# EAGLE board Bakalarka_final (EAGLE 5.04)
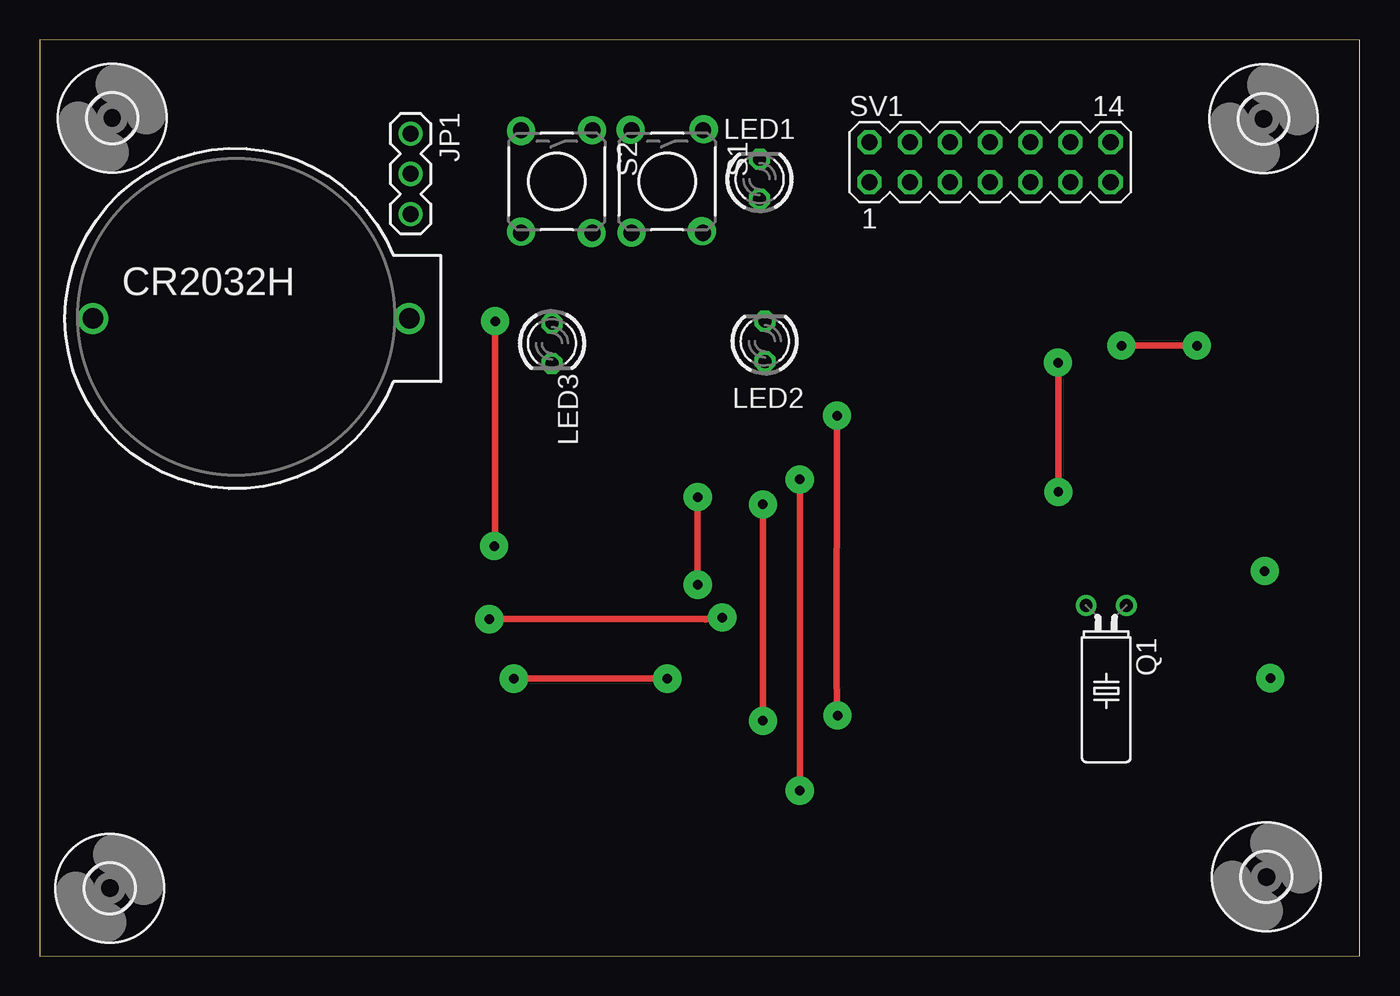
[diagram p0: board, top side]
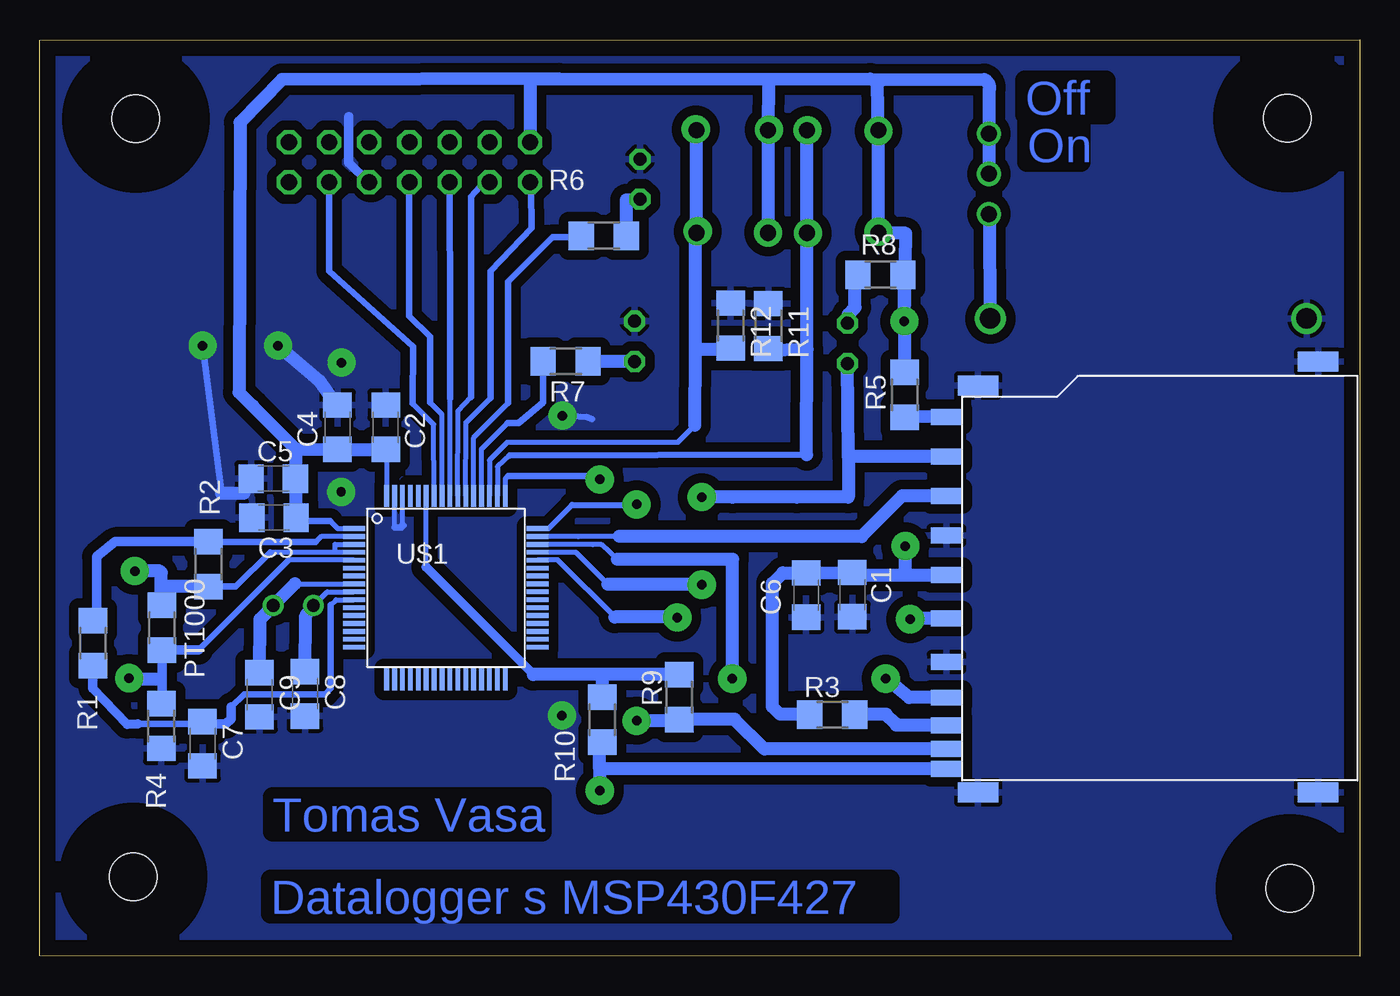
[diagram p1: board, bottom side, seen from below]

Size 83.52 x 57.98 mm. Coordinates in mm from the lower left corner, seen from the top.
Outline: 0,0 83.52,0.03 83.52,57.93 0,57.98 0,0
Copper layers (1*16): Top 0.035mm / dielectric 1.5mm / Bottom 0.035mm
Design rules "default": minimum track width 10mil, minimum drill 24mil, track to track 8mil, track to pad 8mil, pad to pad 8mil, via to via 8mil, smd to smd 8mil, copper to edge 40mil, drill to drill 8mil, minimum pad ring 10mil, minimum via ring 8mil, stop-mask expansion 4mil, vias tented up to drill 0mil, thermal gap 10mil

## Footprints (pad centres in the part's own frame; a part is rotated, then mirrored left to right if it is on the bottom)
C1206 = smd 1.6 x 1.8: 1 -1.4,0; 2 1.4,0
BATTCOM_20MM_PTH = drill 1.3 round: 1 20,0; 2 0,0
1X03 = drill 1.016 round: 1 0,0; 2 2.54,0; 3 5.08,0
LED3MM = drill 0.813 octagon: A -1.27,0; K 1.27,0
R1206 = smd 1.6 x 1.803: 1 -1.422,0; 2 1.422,0
TC38H = drill 0.813 round: 1 -1.27,0; 2 1.27,0
TACTILE-PTH = drill 1.016 round: 1 -3.251,2.261; 2 3.251,2.261; 3 -3.251,-2.261; 4 3.251,-2.261
MA07-2 = drill 1.016 octagon: 1 -7.62,-1.27; 2 -7.62,1.27; 3 -5.08,-1.27; 4 -5.08,1.27; 5 -2.54,-1.27; 6 -2.54,1.27; 7 0,-1.27; 8 0,1.27; 9 2.54,-1.27; 10 2.54,1.27; 11 5.08,-1.27; 12 5.08,1.27; 13 7.62,-1.27; 14 7.62,1.27
PM/PAG64 = smd 1.4 x 0.3: 1 -5.8,3.75; 2 -5.8,3.25; 3 -5.8,2.75; 4 -5.8,2.25; 5 -5.8,1.75; 6 -5.8,1.25; 7 -5.8,0.75; 8 -5.8,0.25; 9 -5.8,-0.25; 10 -5.8,-0.75; 11 -5.8,-1.25; 12 -5.8,-1.75; 13 -5.8,-2.25; 14 -5.8,-2.75; 15 -5.8,-3.25; 16 -5.8,-3.75; 33 5.8,-3.75; 34 5.8,-3.25; 35 5.8,-2.75; 36 5.8,-2.25; 37 5.8,-1.75; 38 5.8,-1.25; 39 5.8,-0.75; 40 5.8,-0.25; 41 5.8,0.25; 42 5.8,0.75; 43 5.8,1.25; 44 5.8,1.75; 45 5.8,2.25; 46 5.8,2.75; 47 5.8,3.25; 48 5.8,3.75 | smd 0.3 x 1.4: 17 -3.75,-5.8; 18 -3.25,-5.8; 19 -2.75,-5.8; 20 -2.25,-5.8; 21 -1.75,-5.8; 22 -1.25,-5.8; 23 -0.75,-5.8; 24 -0.25,-5.8; 25 0.25,-5.8; 26 0.75,-5.8; 27 1.25,-5.8; 28 1.75,-5.8; 29 2.25,-5.8; 30 2.75,-5.8; 31 3.25,-5.8; 32 3.75,-5.8; 49 3.75,5.8; 50 3.25,5.8; 51 2.75,5.8; 52 2.25,5.8; 53 1.75,5.8; 54 1.25,5.8; 55 0.75,5.8; 56 0.25,5.8; 57 -0.25,5.8; 58 -0.75,5.8; 59 -1.25,5.8; 60 -1.75,5.8; 61 -2.25,5.8; 62 -2.75,5.8; 63 -3.25,5.8; 64 -3.75,5.8
3,0 = hole 3: 0,0
SDSOCKET1 = smd 1 x 2: CLK -2.45,17.11; CS 7.8,17.11; DAT1 -9.2,17.11; DAT2 10.3,17.11; DI 5.3,17.11; DO -7.45,17.11; INS -10.7,17.11; VCC 0.3,17.11; VSS 2.8,17.11; VSS1 -5.2,17.11; WP -11.95,17.11 | smd 1.27 x 2.54: PAT1 -13.45,15.11; PAT2 -13.45,-6.39; PAT3 13.8,-6.39; PAT4 12.3,15.11

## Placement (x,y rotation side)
C1  1u  [C1206]  32.11,22.86 270 bottom
C2  1u  [C1206]  61.62,33.45 90 bottom
C3  1u  [C1206]  68.68,27.74 180 bottom
C4  0.01u  [C1206]  64.67,33.45 90 bottom
C5  0.01u  [C1206]  68.73,30.2 180 bottom
C6  0.01u  [C1206]  35.03,22.83 270 bottom
C7  100n  [C1206]  73.2,13.44 270 bottom
C8  5p  [C1206]  66.73,16.59 270 bottom
C9  5p  [C1206]  69.6,16.54 270 bottom
CR2032H  [BATTCOM_20MM_PTH]  3.38,40.34 0 top
JP1  [1X03]  23.47,52.02 270 top
LED1  [LED3MM]  45.54,49.15 90 top
LED2  [LED3MM]  45.87,38.89 90 top
LED3  [LED3MM]  32.41,38.76 270 top
PT1000  1k  [R1206]  75.77,20.78 90 bottom
Q1  32.768kHz  [TC38H]  67.46,22.17 180 top
R1  5k  [R1206]  80.14,19.79 270 bottom
R2  1k  [R1206]  72.82,24.79 90 bottom
R3  50k  [R1206]  33.38,15.27 180 bottom
R4  5k  [R1206]  75.82,14.55 90 bottom
R5  50k  [R1206]  28.8,35.51 90 bottom
R6  330  [R1206]  47.83,45.57 180 bottom
R7  330  [R1206]  50.24,37.62 180 bottom
R8  330  [R1206]  30.33,43.1 0 bottom
R9  100k  [R1206]  43.05,16.38 90 bottom
R10  100k  [R1206]  47.93,14.96 90 bottom
R11  100k  [R1206]  37.41,39.85 270 bottom
R12  100k  [R1206]  39.8,39.88 270 bottom
S1  [TACTILE-PTH]  39.7,49 270 top
S2  [TACTILE-PTH]  32.72,49 270 top
SV1  [MA07-2]  60.12,50.22 0 top
U$1  F42X---PM64  [PM/PAG64]  57.81,23.29 0 bottom
U$2  [3,0]  4.6,53.01 0 top
U$3  SDSOCKET1  [SDSOCKET1]  9.04,23.8 90 bottom
U$4  [3,0]  77.42,52.96 0 top
U$5  [3,0]  77.6,5 0 top
U$6  [3,0]  4.45,4.29 0 top

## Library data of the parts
C1-C9 PT1000 R1-R12 = rcl
CR2032H JP1 S1 S2 = SparkFun
LED1-LED3 = led
Q1 = crystal
SV1 = con-lstb
U$1 = TI_MSP430_v13
U$2 U$4-U$6 = holes
U$3 = SDSOCKET

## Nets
A0+: R1.1 R2.2 U$1.2
A0-/A1+: PT1000.2 R2.1 U$1.3 U$1.4
A1-: PT1000.1 R4.2 U$1.5
BUT1: R12.2 S1.1 S1.2 U$1.51
BUT2: R11.2 S2.1 S2.2 U$1.50
CD: R9.1 U$1.48 U$3.INS
CON: R9.2 R10.2 U$1.59
GND: C1.2 C2.2 C3.2 C4.2 C5.2 C6.2 C7.2 C8.2 C9.2 CR2032H.2 LED1.K LED2.K R4.1 R11.1 R12.1 SV1.9 U$1.62 U$1.63 U$3.PAT1 U$3.PAT2 U$3.PAT3 U$3.PAT4 U$3.VSS U$3.VSS1
LED1: R6.2 U$1.53
LED2: R7.2 U$1.52
N$1: C9.1 Q1.1 U$1.8
N$2: C8.1 Q1.2 U$1.9
N$3: CR2032H.1 JP1.3
N$4: R3.1 U$3.DAT1
N$5: R5.1 U$3.DAT2
N$6: LED1.A R6.1
N$7: LED2.A R7.1
N$8: LED3.A R8.1
RST: SV1.11 U$1.58
SDCS: LED3.K U$1.45 U$3.CS
SIMO: U$1.47 U$3.DI
SOMI: U$1.46 U$3.DO
TCK: SV1.7 U$1.57
TDI: SV1.3 U$1.55
TDO: SV1.1 U$1.54
TMS: SV1.5 U$1.56
UCLK: U$1.44 U$3.CLK
V+: C1.1 C2.1 C3.1 C4.1 C5.1 C6.1 JP1.1 JP1.2 R3.2 R5.2 R8.2 S1.3 S1.4 S2.3 S2.4 SV1.2 U$1.1 U$1.64 U$3.VCC
VREF: C7.1 R1.2 U$1.10
WP: R10.1 U$1.49 U$3.WP

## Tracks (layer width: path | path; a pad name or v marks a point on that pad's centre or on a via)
A0+
  Bottom 0.305: U$1.2 65.71,26.54 66.06,26.19 | 72.8,26.19 R2.2 | 79.91,21.34 R1.1
  Bottom 0.406: 66.06,26.19 72.8,26.19
  Bottom 0.61: R2.2 78.72,26.21 79.91,25.27 79.91,21.34
A0-/A1+
  Bottom 0.305: U$1.3 64.82,26.04 64.82,25.54 | 64.82,25.54 U$1.4 | 64.82,25.54 68.92,25.54 | R2.1
  Bottom 0.406: 68.92,25.54 71.09,23.37 R2.1
  Bottom 0.61: 75.77,23.37 PT1000.2
  Bottom 0.813: R2.1 75.77,23.37
A1-
  Bottom 0.305: 75.77,16.33 R4.2 | U$1.5 67.77,25.04 | PT1000.1
  Bottom 0.406: 67.77,25.04 73.46,19.35
  Bottom 0.61: PT1000.1 75.77,16.33 | 73.46,19.35 PT1000.1
BUT1
  Bottom 0.305: U$1.51 55.06,31.38 53.95,32.49 43.16,32.49 42.06,33.58
  Bottom 0.813: 42.06,33.58 42.04,38.4 | 42.04,38.4 42.01,45.69 S1.2 S1.1 | R12.2 40.03,38.4 42.04,38.4
BUT2
  Bottom 0.305: 53.77,31.67 54.56,30.96 54.56,29.17 U$1.50
  Bottom 0.406: 35,31.72 53.77,31.67
  Bottom 0.813: S2.1 S2.2 34.98,38.38 | 35,31.72 34.98,38.38 | R11.2 37.64,38.3 34.98,38.38
CD  (via drill 0.6 pad 1.78)
  Top 0.406: v45.74,14.88 45.75,18.92 v45.74,28.57
  Bottom 0.305: U$1.48 51.32,27.04 49.84,28.52
  Bottom 0.406: 49.84,28.52 46.1,28.5 v45.74,28.57
  Bottom 0.813: U$3.INS 37.66,13.1 39.55,14.99 39.55,14.96 R9.1 43.05,14.88 v45.74,14.88
CON
  Bottom 0.305: 59.08,24.61 59.08,29.07 U$1.59
  Bottom 0.61: 52.27,17.81 59.08,24.61
  Bottom 0.813: R9.2 47.93,17.8 47.93,17.81 | 47.93,17.81 R10.2 | 47.93,17.81 52.27,17.81
GND  (via drill 0.6 pad 1.78)
  Top 0.406: v73.2,38.61 v68.43,38.61 | v50.44,34.19 50.42,17.48 v50.47,15.21
  Bottom 0.305: 61.06,27.1 U$1.63 | 60.56,27.29 U$1.62
  Bottom 0.406: 72.01,29.26 v73.2,38.61 | 70.59,29.26 arc-45 70.41,29.34 C5.2 | 61.06,27.1 60.63,27.1 60.5,27.23 60.56,27.29 | 48.56,33.96 48.92,34.09 v50.44,34.19 | 64.87,35.05 C4.2 | SV1.9 62.71,48.95 | 63.96,53.09 63.88,53.16
  Bottom 0.61: 62.71,48.95 63.96,50.19 63.96,53.09
  Bottom 0.813: v68.43,38.61 65.86,36.43 64.87,35.05 | 70.59,29.26 72.01,29.26
  other vias: 64.41,37.54 64.44,29.36
  pour Bottom (isolate 0.61): 0.13,0.18 80.14,0.36 83.16,0.36 83.16,0.66 83.19,4.45 83.19,57.56 0.25,57.66 arc90 0,57.4
LED1
  Bottom 0.305: U$1.53 56.06,32.79 53.87,34.98
  Bottom 0.406: R6.2 49.33,45.49 51.05,45.49 53.87,42.67 53.87,34.98
LED2
  Bottom 0.305: U$1.52 55.56,32.07 53.92,33.71
  Bottom 0.406: 53.92,33.71 53.21,33.73 51.66,35 R7.2
N$1
  Bottom 0.305: 67.36,23.54 U$1.8
  Bottom 0.813: 67.36,23.54 Q1.1 69.57,21.31 C9.1
N$2
  Bottom 0.305: U$1.9 65.33,23.04 Q1.2
  Bottom 0.813: Q1.2 66.67,21.54 C8.1
N$3
  Bottom 0.406: JP1.3 23.47,46.78 arc-45 23.39,46.6
  Bottom 0.813: CR2032H.1 23.39,46.6
N$4
  Bottom 0.813: U$3.DAT1 29.34,14.6 29.34,14.71 29.39,14.71 29.97,15.29 31.57,15.29 R3.1
N$5
  Bottom 0.406: 28.7,34.13 R5.1
  Bottom 0.813: U$3.DAT2 28.7,34.13
N$6
  Bottom 0.813: LED1.A 46.41,47.83 R6.1
N$7
  Bottom 0.813: LED2.A R7.1
N$8
  Bottom 0.813: R8.1 31.93,43.1 31.93,41.02 32.36,40.59 LED3.A
N$10
  Top 0.406: 64.44,29.36 64.44,37.46
  Top 0.61: 64.44,37.46 64.41,37.49
N$11  (via drill 0.6 pad 1.78)
  other vias: 77.5,24.36
N$12  (via drill 0.6 pad 1.78)
  other vias: 77.85,17.58
N$13
  Bottom 0.813: 75.82,22.28 75.82,24.26
N$14
  Bottom 0.406: 75.79,19.18 75.82,19.3
N$15
  Bottom 0.813: 75.89,24.36 77.55,24.36
N$16
  Bottom 0.813: 77.72,17.53 75.87,17.53 75.87,17.5
RST
  Bottom 0.305: U$1.58 | U$1.58 58.59,33.63 59.92,34.95
  Bottom 0.406: SV1.11 65.2,45.77 65.2,43.33 59.89,38.56 59.92,34.95 | SV1.11 65.15,49.02 | SV1.11
S$1  (via drill 0.6 pad 1.78)
  other vias: 34.92,45.72
S$2  (via drill 0.6 pad 1.78)
  other vias: 41.88,45.85
S$3  (via drill 0.6 pad 1.78)
  other vias: 37.39,52.27
S$4  (via drill 0.6 pad 1.78)
  other vias: 42.01,52.3
S$5  (via drill 0.6 pad 1.78)
  other vias: 34.95,52.25
S$6  (via drill 0.5 pad 1.27)
  other vias: 66.17,22.17
S$7  (via drill 0.5 pad 1.27)
  other vias: 68.76,22.15
S$8  (via drill 0.5 pad 1.27)
  other vias: 23.37,40.34
S$9  (via drill 0.5 pad 1.27)
  other vias: 23.44,52.02
S$10  (via drill 0.5 pad 1.27)
  other vias: 23.5,49.5
S$11  (via drill 0.5 pad 1.27)
  other vias: 23.44,46.99
S$12  (via drill 0.5 pad 1.27)
  other vias: 52.37,51.46
S$13  (via drill 0.5 pad 1.27)
  other vias: 52.43,48.95
S$14  (via drill 0.5 pad 1.27)
  other vias: 54.97,48.95
S$15  (via drill 0.5 pad 1.27)
  other vias: 54.91,51.54
S$16  (via drill 0.5 pad 1.27)
  other vias: 57.48,51.46
S$17  (via drill 0.5 pad 1.27)
  other vias: 57.45,48.95
S$18  (via drill 0.5 pad 1.27)
  other vias: 59.97,51.49
S$19  (via drill 0.5 pad 1.27)
  other vias: 59.99,49
S$20  (via drill 0.5 pad 1.27)
  other vias: 62.56,48.92
S$21  (via drill 0.5 pad 1.27)
  other vias: 62.53,51.54
S$22  (via drill 0.5 pad 1.27)
  other vias: 65.13,51.49
S$23  (via drill 0.5 pad 1.27)
  other vias: 65.07,48.97
S$24  (via drill 0.5 pad 1.27)
  other vias: 67.61,48.95
S$25  (via drill 0.5 pad 1.27)
  other vias: 67.61,51.46
SDCS  (via drill 0.6 pad 1.78)
  Top 0.406: v41.63,29.03 v41.63,23.49
  Bottom 0.305: U$1.45 49.6,25.54 47.57,23.52
  Bottom 0.406: 39.67,29.03 39.7,29.03 | 35.61,29.03 35.59,29.06
  Bottom 0.813: 39.67,29.03 35.61,29.03 32.36,29.03 32.36,31.67 | 39.7,29.03 v41.63,29.03 | v41.63,23.49 47.57,23.52 | 32.36,31.67 LED3.K | U$3.CS 32.36,31.6 32.36,31.67
SIMO
  Bottom 0.305: U$1.47 49.43,26.54 46.84,26.54
  Bottom 0.406: U$3.DI 26.16,29.11 | 31.52,26.54 31.6,26.54
  Bottom 0.813: 31.52,26.54 28.96,29.11 26.16,29.11 | 31.6,26.54 46.84,26.54
SOMI  (via drill 0.6 pad 1.78)
  Top 0.406: v30,17.55 v39.7,17.55
  Bottom 0.305: U$1.46 48.6,26.04 48.51,26.03 47.98,26.03 46.97,25.1
  Bottom 0.406: v39.7,17.55 39.57,18.82
  Bottom 0.813: 46.97,25.1 39.67,25.1 v39.7,17.55 | U$3.DO 28.52,16.35 v30,17.55
TCK
  Bottom 0.305: U$1.57 58.06,34.26 58.83,35.03
  Bottom 0.406: 58.83,35.03 58.83,39.19 60.15,40.49 60.15,48.92 SV1.7
TDI
  Bottom 0.305: U$1.55 57.05,34.47 56.21,35.36
  Bottom 0.406: SV1.3 55.4,48.95 56.21,48.03 56.21,35.36
TDO
  Bottom 0.305: U$1.54 56.54,33.76 54.99,35.31
  Bottom 0.406: 54.99,35.31 54.99,43.33 52.4,46.05 52.43,48.51 52.45,48.92 52.48,48.95 SV1.1
TMS
  Bottom 0.305: U$1.56 57.56,35.26
  Bottom 0.406: 57.56,35.26 57.56,40.67 57.58,48.51 57.58,48.92 57.53,48.89 SV1.5
UCLK  (via drill 0.6 pad 1.78)
  Top 0.406: v28.45,21.31 42.11,21.31 | 42.11,21.31 42.11,21.29 | 42.11,21.31 43.18,21.31 v43.18,21.41
  Bottom 0.305: U$1.44 50.7,25.04 50.7,24.99 50.67,24.99 47.12,21.44
  Bottom 0.406: 28.45,21.35 v28.45,21.31 | 43.08,21.41 v43.18,21.41 43.2,21.44
  Bottom 0.813: U$3.CLK 28.45,21.35 | 43.2,21.44 47.12,21.44
V+  (via drill 0.6 pad 1.78)
  Top 0.406: v28.75,25.93 28.82,25.91 v28.82,40.16
  Bottom 0.305: 67.3,27.52 67.13,27.56 67.08,27.51 | 65.13,27.51 64.66,27.04 U$1.1 | U$1.64 61.56,31.99 C2.1
  Bottom 0.406: 30.5,55.09 30.96,55.47 | C1.1 31.93,24.1 | 70.03,34.8 arc-45 70,34.86 | 67.08,27.51 65.13,27.51 | C3.1 67.3,27.52 | v28.82,40.16 28.82,40.84 28.82,40.9 v28.82,40.16
  Bottom 0.813: C2.1 C4.1 67.31,32.08 | C3.1 C5.1 67.31,32.08 | JP1.2 JP1.1 23.47,54.74 arc-90 23.77,55.45 30.96,55.47 37.41,55.45 | 67.31,32.08 70.03,34.8 70.89,35.66 70.84,52.73 68.17,55.45 50.65,55.5 52.48,55.47 | 30.5,55.09 S2.3 v30.45,52.2 v30.45,45.82 S2.4 28.73,45.72 v28.82,40.16 | 37.41,55.45 S1.3 v37.44,45.77 S1.4 | 37.41,55.45 52.48,55.47 | C1.1 C6.1 36.5,24.23 37.16,23.57 37.16,15.77 36.68,15.29 34.82,15.29 R3.2 | 31.93,24.1 28.83,24.1 | 28.83,24.1 U$3.VCC | 28.82,40.84 R5.2 | v28.75,25.93 28.75,24.18 28.83,24.1 | 28.82,40.9 28.82,43.01 R8.2 | 52.48,55.47 52.48,51.51 SV1.2
VREF
  Bottom 0.305: U$1.10 64.76,22.54 65.1,22.2 | 73.05,14.68 C7.1
  Bottom 0.406: 65.1,22.2 65.1,16.92 65.46,16.56 70.59,16.56 71.4,15.75 | 73.86,14.68 77.29,14.68 | C7.1 73.38,14.66
  Bottom 0.61: 71.4,15.75 71.4,15.01 71.73,14.68 73.05,14.68 | R1.2 80.14,16.94 77.98,14.66 77.29,14.68 | 73.38,14.66 73.86,14.66 73.86,14.68
WP  (via drill 0.6 pad 1.78)
  Top 0.406: v48.08,10.46 v48.08,30.15
  Bottom 0.305: 53.87,30.35 54.06,30.19 54.06,29.11 U$1.49
  Bottom 0.406: v48.08,30.15 48.28,30.35 53.87,30.35
  Bottom 0.813: 48.08,11.84 v48.08,10.46 | 48.08,11.84 48.08,13.54 R10.1 | U$3.WP 48.07,11.85 48.08,11.84

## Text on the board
Bottom: Off | On | Tomas Vasa | Datalogger s MSP430F427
